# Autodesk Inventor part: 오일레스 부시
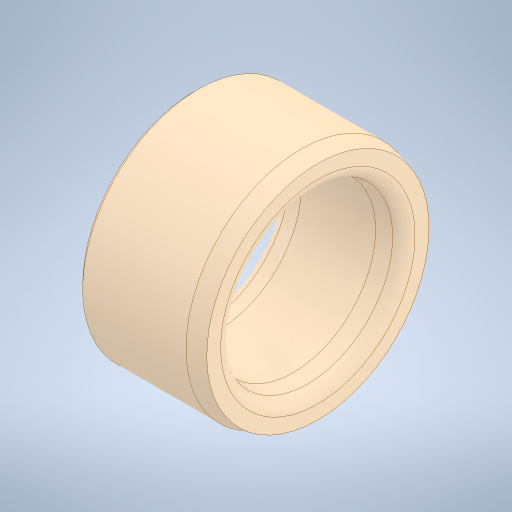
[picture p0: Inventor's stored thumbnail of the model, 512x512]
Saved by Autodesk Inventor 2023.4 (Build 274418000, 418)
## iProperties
Created: 2024-05
Part Number: 오일레스 부시
Material: 구리, 합금
Document SubType Name: Modeling
Designer: EDU-001
Density: 8.92 g/cm^3
Appearance: 기본값
Author: jhkim
Sending System: Autodesk Inventor 2025
Preprocessor: ST-DEVELOPER v20
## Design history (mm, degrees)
node "오일레스 부시1"
node "솔리드2"
node "솔리드1"
